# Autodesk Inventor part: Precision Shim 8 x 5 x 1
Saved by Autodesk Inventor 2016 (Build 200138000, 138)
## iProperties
Created: 2016-03
Part Number: Precision Shim 8 x 5 x 1
Material: Generic
Document SubType Name: Modeling
Designer: bongo_000
Density: 1 g/cm^3
Appearance: Default
Author: bongo_000
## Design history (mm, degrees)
feature "BOSS-EXTRUDE1"
body "Solid1"
